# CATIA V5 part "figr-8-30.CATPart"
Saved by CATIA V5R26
Part number: Part1
Bounding box of the stored display mesh (mm): x -50 to 50, y -75 to 125, z 0 to 40
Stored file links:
  D:\_Deepak\CATIA\CATIA V5-6R2016_Deepak\Resources\Part files\Partfiles\c08_catia_v5_6r2016_prt\figr-8-30.CATPart
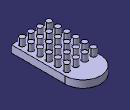
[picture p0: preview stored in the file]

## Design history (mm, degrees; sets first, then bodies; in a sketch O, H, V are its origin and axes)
Body1 (main body)
  Sketch1 on xy-plane, origin (0, 0, 0), H (1, 0, 0), V (0, 1, 0)
    line L1 (50, 75) -> (50, -75)
    line L2 (50, -75) -> (-50, -75)
    line L3 (-50, -75) -> (-50, 75)
    arc A1 centre (0, 75) radius 50 from (-50, 75) to (50, 75) cw
    point P5 (0, 75)
    axis line L4 (50, -75) -> (-50, 75)
    length L2 = 100
    distance P5 L2 = 150
    horizontal: L2 H
    vertical: L1 V, L3 V
    tangency: A1 L3, A1 L1
    midpoint: O L4
  Pad1: profile Sketch1, direction (0, 0, 1), length 20
  Sketch2 on face of Pad1, origin (0, 0, 20), H (1, 0, 0), V (0, 1, 0)
    circle A1 centre (35, -60) radius 7.5
    point P1 (35, -60)
    reference projected line E1 (-50, -75) -> (50, -75) from edge [face of Pad1 | face of Pad1]
    reference projected line E2 (50, -75) -> (50, 75) from edge [face of Pad1 | face of Pad1]
    distance P1 E1 = 15
    distance P1 E2 = 15
    radius A1 = 7.5
  Pad2: profile Sketch2, direction (0, 0, 1), length 20
  RectPattern1: of Pad2, direction 1 instances 4, spacing 25, along edge [face of Pad1 | face of Pad1] reversed, direction 2 instances 6, spacing 25, along edge [face of Pad1 | face of Pad1]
